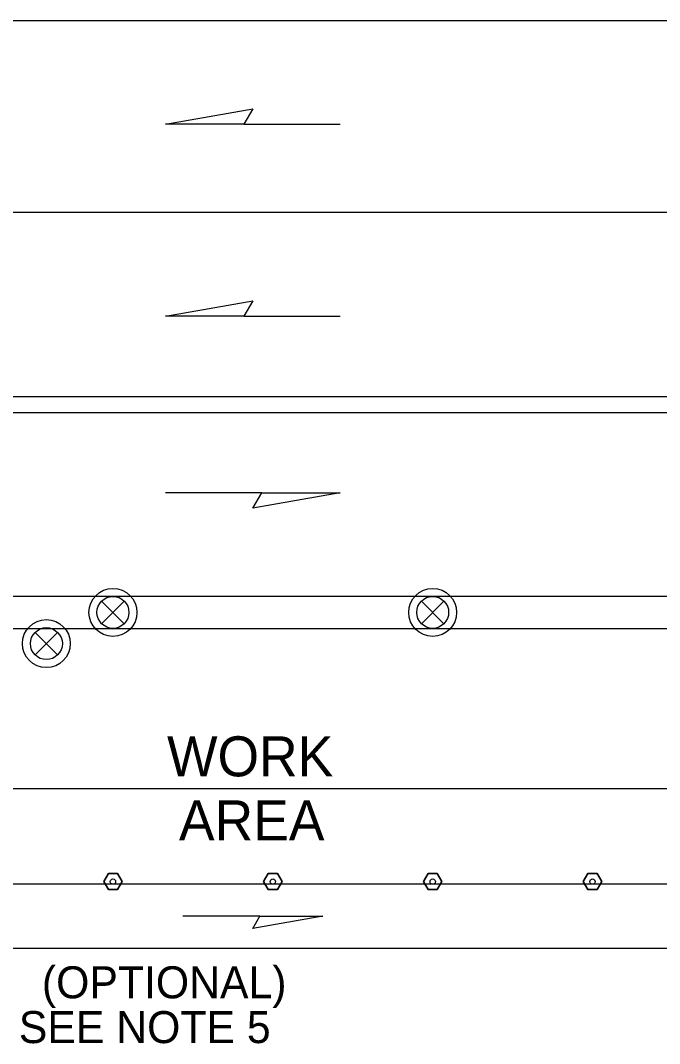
# Model space of a CAD drawing. Extents: x 99958 to 100176, y 99935 to 100011.
# Drawn here: x 100011.132 to 100012.731, y 99974.498 to 99977.056 of the extents above; entities that cross this region are included whole.
import ezdxf

# ---------------------------------------------------------------- set-up
doc = ezdxf.new("R2010")
doc.units = 0
for name, color, linetype in [('RD_ED_ShoulderPavedEdge', 7, 'Continuous'), ('RD_MK_LineDblYellowCenter', 7, 'Continuous'), ('RD_MK_LineEdgeWhite', 7, 'Continuous'), ('RD_MK_LineLane', 7, 'Continuous'), ('TR_WZ_TrafficSafetyDrum', 7, 'Continuous'), ('TR_WZ_TubularMarker', 7, 'Continuous'), ('TR_WZ_WorkAreaLabel', 7, 'Continuous'), ('TR_WZ_WorkZoneDetails', 7, 'Continuous'), ('TR_WZ_WorkZoneTextCurrent', 7, 'Continuous')]:
    doc.layers.add(name, color=color, linetype=linetype)

msp = doc.modelspace()

# ---------------------------------------------------------------- linework, layer by layer
at = {"layer": 'RD_ED_ShoulderPavedEdge'}
msp.add_line((100000.8283, 99974.7357), (100014.8933, 99974.7357), dxfattribs=at)
at = {"layer": 'RD_MK_LineDblYellowCenter'}
for p, q in [((100000.8283, 99976.1157), (100014.914, 99976.1157)), ((100000.8283, 99976.0757), (100014.8726, 99976.0757))]:
    msp.add_line(p, q, dxfattribs=at)
at = {"layer": 'RD_MK_LineEdgeWhite'}
for p, q in [((100000.8283, 99977.0557), (100014.8933, 99977.0557)), ((100000.8283, 99975.1357), (100014.8933, 99975.1357))]:
    msp.add_line(p, q, dxfattribs=at)
at = {"layer": 'RD_MK_LineLane'}
for points in [[(100014.8933, 99976.5757), (100000.8283, 99976.5757)], [(100014.8933, 99975.6157), (100000.8283, 99975.6157)]]:
    msp.add_lwpolyline(points, dxfattribs=at)
at = {"layer": 'TR_WZ_TrafficSafetyDrum'}
for p, q in [((100011.3353, 99975.604), (100011.3919, 99975.5474)), ((100011.3919, 99975.604), (100011.3353, 99975.5474)), ((100012.1353, 99975.604), (100012.1919, 99975.5474)), ((100012.1919, 99975.604), (100012.1353, 99975.5474)), ((100011.2252, 99975.4692), (100011.1686, 99975.5257)), ((100011.1686, 99975.4692), (100011.2252, 99975.5257))]:
    msp.add_line(p, q, dxfattribs=at)
for centre, radius in [((100011.3636, 99975.5757), 0.06), ((100011.3636, 99975.5757), 0.06), ((100012.1636, 99975.5757), 0.06), ((100012.1636, 99975.5757), 0.06), ((100011.3636, 99975.5757), 0.04), ((100012.1636, 99975.5757), 0.04), ((100011.1969, 99975.4975), 0.06), ((100011.1969, 99975.4975), 0.06), ((100011.1969, 99975.4975), 0.04)]:
    msp.add_circle(centre, radius, dxfattribs=at)
at = {"layer": 'TR_WZ_TubularMarker'}
for points in [[(100011.3405, 99974.9024), (100011.3521, 99974.9224), (100011.3752, 99974.9224), (100011.3867, 99974.9024), (100011.3752, 99974.8824), (100011.3521, 99974.8824)], [(100011.7405, 99974.9024), (100011.7521, 99974.9224), (100011.7752, 99974.9224), (100011.7867, 99974.9024), (100011.7752, 99974.8824), (100011.7521, 99974.8824)], [(100012.1405, 99974.9024), (100012.1521, 99974.9224), (100012.1752, 99974.9224), (100012.1867, 99974.9024), (100012.1752, 99974.8824), (100012.1521, 99974.8824)], [(100012.5405, 99974.9024), (100012.5521, 99974.9224), (100012.5752, 99974.9224), (100012.5867, 99974.9024), (100012.5752, 99974.8824), (100012.5521, 99974.8824)]]:
    msp.add_lwpolyline(points, close=True, dxfattribs=at)
for points in [[(100011.3521, 99974.8824), (100011.3752, 99974.8824), (100011.3867, 99974.9024), (100011.3752, 99974.9224), (100011.3521, 99974.9224), (100011.3405, 99974.9024), (100011.3521, 99974.8824)], [(100011.7521, 99974.8824), (100011.7752, 99974.8824), (100011.7867, 99974.9024), (100011.7752, 99974.9224), (100011.7521, 99974.9224), (100011.7405, 99974.9024), (100011.7521, 99974.8824)], [(100012.1521, 99974.8824), (100012.1752, 99974.8824), (100012.1867, 99974.9024), (100012.1752, 99974.9224), (100012.1521, 99974.9224), (100012.1405, 99974.9024), (100012.1521, 99974.8824)], [(100012.5521, 99974.8824), (100012.5752, 99974.8824), (100012.5867, 99974.9024), (100012.5752, 99974.9224), (100012.5521, 99974.9224), (100012.5405, 99974.9024), (100012.5521, 99974.8824)]]:
    msp.add_lwpolyline(points, dxfattribs=at)
for centre in [(100011.3636, 99974.9024), (100011.7636, 99974.9024), (100012.1636, 99974.9024), (100012.5636, 99974.9024)]:
    msp.add_circle(centre, 0.00667, dxfattribs=at)
at = {"layer": 'TR_WZ_WorkZoneDetails'}
for p, q in [((100011.6913, 99976.7964), (100011.9324, 99976.7964)), ((100011.6913, 99976.3164), (100011.9324, 99976.3164)), ((100011.7359, 99975.875), (100011.4948, 99975.875)), ((100011.7314, 99974.8157), (100011.5385, 99974.8157))]:
    msp.add_line(p, q, dxfattribs=at)
for points in [[(100011.4948, 99976.7964), (100011.7136, 99976.835), (100011.6913, 99976.7964)], [(100011.4948, 99976.3164), (100011.7136, 99976.355), (100011.6913, 99976.3164)], [(100011.9324, 99975.875), (100011.7136, 99975.8364), (100011.7359, 99975.875)], [(100010.4636, 99974.8957), (100010.4636, 99975.5357), (100012.9636, 99975.5357), (100012.9636, 99974.8957)], [(100011.8886, 99974.8157), (100011.7136, 99974.7849), (100011.7314, 99974.8157)]]:
    msp.add_lwpolyline(points, close=True, dxfattribs=at)

# ---------------------------------------------------------------- texts
at = {"layer": 'TR_WZ_WorkAreaLabel'}
for s, p in [('WORK', (100011.499, 99975.1657)), ('AREA', (100011.5287, 99975.0057))]:
    msp.add_text(s, height=0.1, dxfattribs=at).set_placement(p)
at = {"layer": 'TR_WZ_WorkZoneTextCurrent'}
for s, p in [('(OPTIONAL)', (100011.1857, 99974.6107)), ('SEE NOTE 5', (100011.128, 99974.4987))]:
    msp.add_text(s, height=0.08, dxfattribs=at).set_placement(p)

doc.saveas('drawing.dxf')
